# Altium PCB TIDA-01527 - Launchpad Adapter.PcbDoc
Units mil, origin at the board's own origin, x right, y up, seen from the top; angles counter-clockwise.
Board outline 2007.87 x 1181.1 mil, 2 copper layers (Top Layer, Bottom Layer), stack 62 mil thick; 19 components, 11 nets, 70 pads, 2 vias.
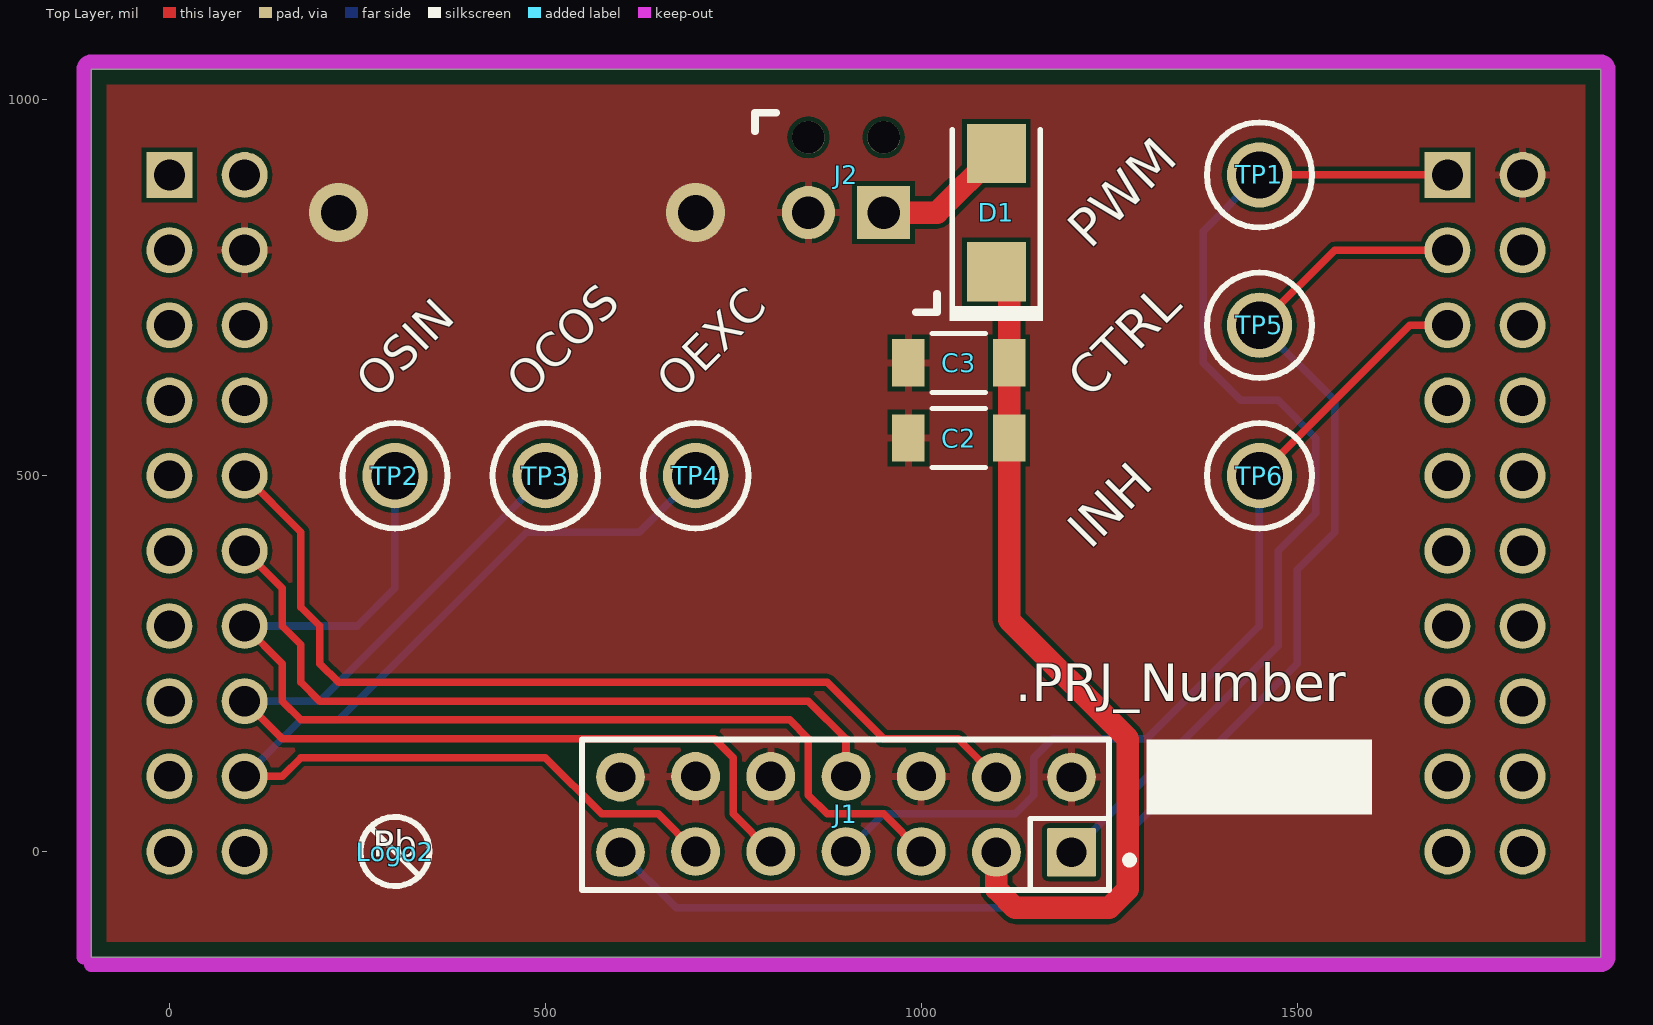
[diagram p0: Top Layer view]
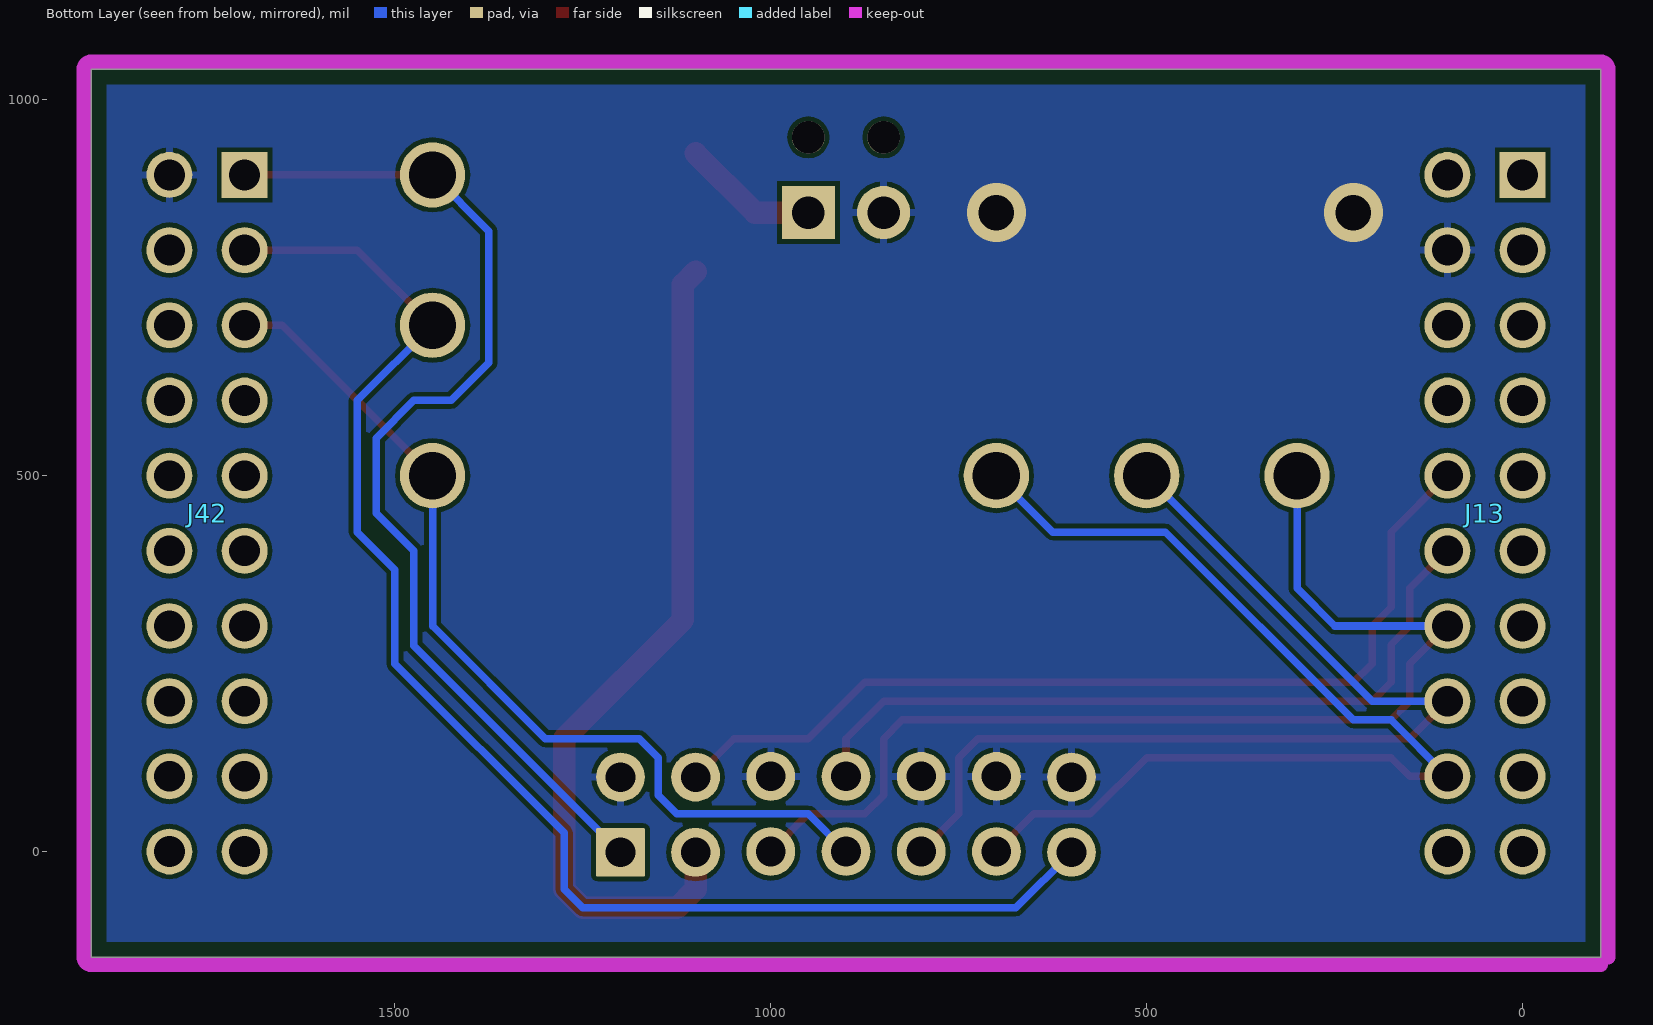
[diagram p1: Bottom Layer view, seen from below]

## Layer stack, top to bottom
Top Solder: solder mask 0.4, Solder Resist, Dk 3.5
Top Layer: signal copper 1.4
Dielectric1: core 59.2, FR-4, Dk 4.8
Bottom Layer: signal copper 1.4
Bottom Solder: solder mask 0.4, Solder Resist, Dk 3.5

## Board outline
-103.94,-140.55 1903.94,-140.55 1903.94,1040.55 -103.94,1040.55

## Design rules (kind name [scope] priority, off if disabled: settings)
Clearance Clearance_to_outline [All vs OnLayer('Keep-Out Layer')] p1: gap=20 ignorepadtopadclearanceinfootprint=FALSE except(0: Arc-Hole Track-Hole SMDPad-Hole THPad-Hole Via-Hole Fill-Hole Poly-Hole Region-Hole Text-Hole)
Clearance [All] p2: gap=6 ignorepadtopadclearanceinfootprint=FALSE except(0: Arc-Hole Track-Hole SMDPad-Hole THPad-Hole Via-Hole Fill-Hole Poly-Hole Region-Hole Text-Hole)
ComponentClearance ComponentClearance_J4&J5 [InComponent('J4') vs InComponent('J5')] p1: gap=0 collisioncheckmode=3 verticalgap=100000 showdistances=FALSE
ComponentClearance [All] p2: gap=10 collisioncheckmode=3 verticalgap=10 showdistances=FALSE
DiffPairsRouting [All] p1: maxlimit=393.7 minlimit=4.92 mostfreqgap=5.91 toplayer_minwidth=15 toplayer_maxwidth=15 toplayer_prefwidth=15 bottomlayer_minwidth=15 bottomlayer_maxwidth=15 bottomlayer_prefwidth=15 maxuncoupledlength=500
FabricationTestPointUsage FabricationTestPointUsage_1 [All] p1: valid=0 allowmultiple=FALSE
FabricationTestpoint FabricationTestpoint_1 [All] p1: side=3 testpointundercomponent=TRUE minsize=40 maxsize=100 preferedsize=60 minholesize=0 maxholesize=40 preferedholesize=32 testpointgrid=1 allowsidetop=TRUE allowsidebottom=TRUE usegrid=TRUE gridtolerance=0.01
HoleSize [All] p1: absolutevalues=TRUE maxlimit=236.22 minlimit=7.87 maxpercent=80.000 minpercent=20.000
HoleSize FabricationTestpoint [All] p2 off: absolutevalues=TRUE maxlimit=100 minlimit=1 maxpercent=80.000 minpercent=20.000
HoleSize FabricationTestPointUsage [All] p3 off: absolutevalues=TRUE maxlimit=100 minlimit=1 maxpercent=80.000 minpercent=20.000
PlaneClearance [All] p1: clearance=19.68
PlaneConnect [All] p1: planeconnectstyle=Relief reliefexpansion=15.75 reliefentries=4 reliefconductorwidth=5.91 reliefairgap=5.91
PolygonConnect PolygonConnect_via [IsVia] p1: connectstyle=Direct reliefconductorwidth=10 reliefentries=4 polygonreliefangle="90 Angle" airgapwidth=10
PolygonConnect [All] p2: connectstyle=Relief reliefconductorwidth=10 reliefentries=4 polygonreliefangle="90 Angle" airgapwidth=6
RoutingCorners [All] p1: cornerstyle=45-Degree minsetback=49.21 maxsetback=49.21
RoutingVias [All] p1: holewidth=12 width=28 viastyle="Through Hole" minholewidth=7.87 minwidth=17.72 maxholewidth=17.72 maxwidth=29.53
SilkToSilkClearance [All] p1: silktosilkclearance=0
SilkToSolderMaskClearance [IsPad] p1: minsilkscreentomaskgap=4 clearancetoexposedcopper=TRUE
SolderMaskExpansion SolderMaskExpansion_vias [IsVia] p1: expansion=-15
SolderMaskExpansion [All] p2: expansion=2.95
Width [All] p1: maxlimit=30 minlimit=8 preferedwidth=10
20 further rules are at their usual default settings.

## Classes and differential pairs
component class "TIDA-01527 - Launchpad Adapter_circuit": C2 C3 D1 J1 J2 J13 J42 TP1 TP2 TP3 TP4 TP5 TP6
component class "TIDA-01527 - Launchpad Adapter_Hardware": Logo2 Logo3 ZZ1 ZZ2 ZZ3 ZZ4
component class AssemblyNote: ZZ1 ZZ2 ZZ3 ZZ4

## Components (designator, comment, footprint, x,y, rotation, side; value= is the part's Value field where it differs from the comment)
C2 "GCM31CR72A105KA03" 1206_180 1050,550 r180 top value=1uF
C3 "GCM31CR72A105KA03" 1206_180 1050,650 r180 top value=1uF
D1 "SS16T3G" SMA 1100,850 r90 top value=60V
J1 "SSQ-107-03-G-D" SSQ-107-03-G-D 900,50 r0 top
J2 "1725656" CONN_1725656 900,850 r180 top
J13 "SSW-110-21-S-D" Samtec_SSW-110-x1-x-D 50,450 r270 bottom locked
J42 "SSW-110-21-S-D" Samtec_SSW-110-x1-x-D 1750,450 r270 bottom locked
Logo2 "Pb-Free Symbol" Pb-Free_Overlay_Small 300,0 r0 top
Logo3 "FCC disclaimer" FCC_disclaimer 1026.06,1229.45 r180 bottom
TP1 "5005" Keystone5005 1450,900 r0 top
TP2 "5005" Keystone5005 300,500 r0 top
TP3 "5005" Keystone5005 500,500 r0 top
TP4 "5005" Keystone5005 700,500 r0 top
TP5 "5005" Keystone5005 1450,700 r0 top
TP6 "5005" Keystone5005 1450,500 r0 top
ZZ1 "This Assembly Note is for PCB labels only" AssemblyNoteLabel 81.06,3797.45 r0 top
ZZ2 "These assemblies are ESD sensitive, ESD precautions shall be observed." AssemblyNote 81.06,3688.56 r0 top
ZZ3 "These assemblies must be clean and free from flux and all contaminants. Use of no clean flux is not acceptable." AssemblyNote 81.06,3600.01 r0 top
ZZ4 "These assemblies must comply with workmanship standards IPC-A-610 Class 2, unless otherwise specified." AssemblyNote 81.06,3511.45 r0 top

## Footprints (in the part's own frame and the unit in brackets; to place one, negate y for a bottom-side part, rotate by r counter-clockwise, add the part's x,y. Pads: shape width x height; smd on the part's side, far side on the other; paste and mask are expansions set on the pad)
1206_180 [mm] "1206_180"
  rect 1.1x1.6 smd: 1(-1.7,0) 2(1.7,0)
  silkscreen extent -0.9,-1 0.9,1, body extent -1.75,-0.95 1.75,0.95, height 1.8
AssemblyNote [mil] "Assembly Note"
AssemblyNoteLabel [mil] "Assembly Note for PCB Labels"
CONN_1725656 [mm] "Phoenix Contact"
  rect 1.8x1.8 hole 1.1: 1(-1.27,0)
  round 1.8 hole 1.1: 2(1.27,0)
  round 1.1 hole 1.1 unplated: MH1(-1.275,-2.54) MH2(1.27,-2.54)
  silkscreen extent -3.08,-3.37 3.08,3.37, body extent -2.77,-3.1 2.77,3.1, height 8.52
FCC_disclaimer [mil]
Keystone5005 [mil] "Keystone Compact loops"
  round 87 hole 63: 1(0,0)
  silkscreen extent -70,-70 70,70, body extent -63,-63 62,63, height 225
Pb-Free_Overlay_Small [mil]
  silkscreen extent -46,-46 46,46
Samtec_SSW-110-x1-x-D [mm] "Receptacle, 2.54mm, 10x2, TH"
  rect 1.55x1.55 hole 1.04: 1(-11.43,1.27)
  round 1.55 hole 1.04: 2(-11.43,-1.27) 3(-8.89,1.27) 4(-8.89,-1.27) 5(-6.35,1.27) 6(-6.35,-1.27) 7(-3.81,1.27) 8(-3.81,-1.27) 9(-1.27,1.27) 10(-1.27,-1.27) 11(1.27,1.27) 12(1.27,-1.27) 13(3.81,1.27) 14(3.81,-1.27) 15(6.35,1.27) 16(6.35,-1.27) 17(8.89,1.27) 18(8.89,-1.27) 19(11.43,1.27) 20(11.43,-1.27)
  body extent -12.95,-2.48 12.95,2.48, height 8.51
SMA [mm] "Molded Diode, 2-Leads, Body 4.3x2.6mm, IPC Medium Density, based on OnSemi component dimensions and land pattern"
  rect 2x2 smd: 1(-2,0) 2(2,0)
  silkscreen extent -3.66,-1.57 2.79,1.57, body extent -2.6,-1.3 2.6,1.3, height 2.42
SSQ-107-03-G-D [mm] "Samtec socket, 100 mil spacing, 2x7"
  rrect6% 1.65x1.65 hole 1: 1(7.62,-1.295)
  round 1.65 hole 1: 2(7.62,1.245) 3(5.08,-1.295) 4(5.08,1.245) 5(2.54,-1.27) 6(2.54,1.27) 7(0,-1.27) 8(0,1.27) 9(-2.54,-1.27) 10(-2.54,1.27) 11(-5.08,-1.27) 12(-5.08,1.27) 13(-7.62,-1.295) 14(-7.62,1.245)
  silkscreen extent -8.92,-2.57 9.71,2.52, body extent -9.14,-2.5 9.14,2.45, height 8.41

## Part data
C2 C3: "CAP, CERM, 1 µF, 100 V,+/- 10%, X7R, AEC-Q200 Grade 1, 1206", Cap_Case=1206, Manufacturer=MuRata, Supplier Part Number 1=GCM31CR72A105KA03L-ND, TempCo=X7R, Tolerance_%=10, Value2=100V, ValueDisplayed=1µF
D1: "Diode, Schottky, 60 V, 1 A, SMA", Manufacturer="ON Semiconductor", Supplier Part Number 1=SS16T3GOSCT-ND, Value1=1A, Value2=0.72V
J1: "Receptacle, 100mil, 7x2, Gold, TH", Manufacturer=Samtec, Supplier Part Number 1=SAM1196-07-ND
J2: "Terminal Block, 100mil, 2x1, 6A, 63V, TH", Manufacturer="Phoenix Contact", Supplier Part Number 1=651-1725656
J13 J42: "Receptacle, 2.54mm, 10x2, Gold, TH", Color=Black, Manufacturer=Samtec, Supplier Part Number 1=SAM1223-10-ND
Logo2: library part Pb-Free
Logo3: library part FCC_disclaimer, "FCC_disclaimer"
TP1 TP2 TP3 TP4 TP5 TP6: "Test Point, Compact, Red, TH", Color=Red, Manufacturer=Keystone, Supplier Part Number 1=36-5005-ND
ZZ1: library part AssemblyNoteLabel, Alternate Manufacturer=-
ZZ2 ZZ3 ZZ4: library part AssemblyNote, Alternate Manufacturer=-

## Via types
v1: diameter 78.74, hole 47.24, Top Layer to Bottom Layer, 2 vias

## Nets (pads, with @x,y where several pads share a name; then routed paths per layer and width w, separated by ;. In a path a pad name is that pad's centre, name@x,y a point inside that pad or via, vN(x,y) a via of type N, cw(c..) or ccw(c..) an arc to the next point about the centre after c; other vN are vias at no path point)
CTRL: J1.13 J42.3 TP5.1 | length 1912.8
  Top Layer w10: TP5.1 1550,800 J42.3
  Bottom Layer w10: J1.13 674,-75 1250,-75 1275,-50 1275,25 1500,250 1500,375 1550,425 1550,600 TP5.1
GND: C2.2 C3.2 J1.2 J1.6 J1.10 J1.12 J1.14 J2.2 J13.4 J42.2
  other v1: 225,850 700,850
INH: J1.7 J42.5 TP6.1 | length 1236.4
  Top Layer w10: TP6.1 1650,700 J42.5
  Bottom Layer w10: J1.7 950,50 1125,50 1150,75 1150,125 1175,150 1300,150 1450,300 TP6.1
NetD1_2: D1.2 J2.1 | length 182.6
  Top Layer w30: J2.1 1021.26,850 D1.2
OCOS: J1.9 J13.16 TP3.1 | length 1351
  Top Layer w10: J13.16 150,150 725,150 750,125 750,50 J1.9
  Bottom Layer w10: J13.16 200,200 TP3.1
OEXC: J1.11 J13.18 TP4.1 | length 1427.8
  Top Layer w10: J13.18 150,100 175,125 500,125 575,50 650,50 J1.11
  Bottom Layer w10: J13.18 175,175 225,175 475,425 625,425 TP4.1
OSIN: J1.5 J13.14 TP2.1 | length 1468.2
  Top Layer w10: J13.14 150,250 150,200 175,175 825,175 850,150 850,75 875,50 950,50 J1.5
  Bottom Layer w10: J13.14 250,300 300,350 TP2.1
PWM: J1.1 J42.1 TP1.1 | length 1408.1
  Top Layer w10: TP1.1 J42.1
  Bottom Layer w10: J1.1 1475,274 1475,400 1525,450 1525,550 1475,600 1425,600 1375,650 1375,825 TP1.1
VCC: C2.1 C3.1 D1.1 J1.3 | length 1138.5
  Top Layer w30: J1.3 1100,-50 1125,-75 1250,-75 1275,-50 1275,150 1116.93,308.07 C2.1 C3.1 1116.93,754.33 D1.1
VREF: J1.4 J13.10 | length 1254
  Top Layer w10: J13.10 175,425 175,325 200,300 200,250 225,225 875,225 950,150 1049,150 J1.4
VREF1/2: J1.8 J13.12 | length 1012.1
  Top Layer w10: J13.12 150,350 150,300 175,275 175,225 200,200 850,200 900,150 J1.8
pads on no net: J2.MH1 J2.MH2 J13.1 J13.2 J13.3 J13.5 J13.6 J13.7 J13.8 J13.9 J13.11 J13.13 J13.15 J13.17 J13.19 J13.20 J42.4 J42.6 J42.7 J42.8 J42.9 J42.10 J42.11 J42.12 J42.13 J42.14 J42.15 J42.16 J42.17 J42.18 J42.19 J42.20

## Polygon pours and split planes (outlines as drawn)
GND on Top Layer "Top Layer-No Net" (solid, pour order 0): -103.94,-140.55 1903.94,-140.55 1903.94,1040.55 -103.94,1040.55
GND on Bottom Layer "Bottom Layer-No Net" (solid, pour order 2): -103.94,-140.55 1903.94,-140.55 1903.94,1040.55 -103.94,1040.55

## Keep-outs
Keep-Out Layer:
  lines w19.68: -113.78,-140.55 -113.78,1040.55 ; -103.94,-150.39 1903.94,-150.39 ; -113.78,1040.55 cw(c-103.94,1040.55) -103.94,1050.39 ; -113.78,1040.55 cw(c-103.94,1040.55) -103.94,1050.39 ; -103.94,1050.39 1903.94,1050.39 ; 1903.94,-150.39 ccw(c1903.94,-140.55) 1913.78,-140.55 ; 1903.94,-150.39 ccw(c1903.94,-140.55) 1913.78,-140.55 ; 1903.94,1050.39 cw(c1903.94,1040.55) 1913.78,1040.55 ; 1903.94,1050.39 cw(c1903.94,1040.55) 1913.78,1040.55 ; 1913.78,-140.55 1913.78,1040.55
  text ".Layer_Name" at 473.06,-999.04 h60

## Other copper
Top Layer:
  text ".Layer_Name" at 473.06,-999.04 h60
Bottom Layer:
  text ".Layer_Name" at 473.06,-999.04 h60

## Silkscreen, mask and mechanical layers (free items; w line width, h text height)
Top Overlay:
  region: 1600,149.21 1300,149.21 1300,49.21 1600,49.21
  text "PWM" at 1225,800 h50 r45
  text "OSIN" at 275,600 h45 r45
  text "OCOS" at 475,600 h45 r45
  text "OEXC" at 675,600 h45 r45
  text "CTRL" at 1225,600 h50 r45
  text "INH" at 1225,400 h50 r45
  text ".PRJ_Number" at 1125,200 h50
  text ".Layer_Name" at 473.06,-999.04 h60
Bottom Overlay:
  text ".Layer_Name" at 473.06,-999.04 h60
Top Paste:
  text ".Layer_Name" at 473.06,-999.04 h60
Bottom Paste:
  text ".Layer_Name" at 473.06,-999.04 h60
Top Solder:
  rectangle: 175,750 750,950
  text ".Layer_Name" at 473.06,-999.04 h60
  text ".Layer_Name" at 473.06,-999.04 h60
Bottom Solder:
  text ".Layer_Name" at 473.06,-999.04 h60
Drill Guide:
  text ".Layer_Name" at 473.06,-999.04 h60
M1 Board Outline:
  the board outline again, w8
  text ".Layer_Name" at 473.06,-999.04 h60
M2 Board Dimensions:
  rectangle: -103.94,-415.55 21.06,-290.55
  rectangle: 21.06,-540.55 396.06,-415.55
  lines w7: -103.94,-415.55 896.06,-415.55 ; 21.06,-540.55 21.06,-290.55 ; 146.06,-540.55 146.06,-290.55 ; 396.06,-540.55 396.06,-290.55 ; 646.06,-540.55 646.06,-290.55 ; -103.94,-540.55 896.06,-540.55 896.06,-290.55 -103.94,-290.55 -103.94,-540.55
  text ".Layer_Name" at 473.06,-999.04 h60
M3 3D STEP Top:
  text ".Layer_Name" at 473.06,-999.04 h60
M4 3D STEP Bottom:
  text ".Layer_Name" at 473.06,-999.04 h60
M5 Assembly Top:
  lines w10: -395.94,-1070.72 6204.06,-1070.72 ; -395.94,-867.38 6206.06,-867.38 ; -395.94,-664.05 -395.94,-1274.05 3609.06,-1274.05 6206.06,-1274.05 6206.06,-664.05 -395.44,-664.05 -395.44,-1274.05 1180.06,-1274.05 ; 2069.06,-1274.05 2069.06,-664.05 ; 3336.06,-867.38 3336.06,-664.05 ; 4176.06,-867.38 4176.06,-664.05 ; 4798.06,-1280.55 4798.06,-1077.72
  text "COMPONENTS MARKED 'DNP' SHOULD NOT BE POPULATED." at 1049.56,-459.05 h60
  text "ASSEMBLY VARIANT:" at 1049.06,-574.55 h60
  text ".VariantName" at 2085.06,-574.55 h60
  text "PCB VIEWED FROM TOP SIDE" at -332.44,-796.22 h60
  text "BOARD #:" at 2144.06,-796.22 h60
  text ".PRJ_Number" at 2689.56,-796.22 h60
  text "REV:" at 3534.06,-796.22 h60
  text ".PCB_Rev" at 3825.56,-796.22 h60
  text "SVN REV:" at 4372.06,-796.22 h60
  text ".VersionControl_RevNumber" at 4878.06,-796.22 h60
  text "TID #:" at 2144.06,-999.55 h60
  text ".TID" at 2689.56,-999.55 h60
  text "PLOT NAME =" at -332.44,-1204.89 h60
  text ".plot_File_Name" at 473.06,-1204.89 h60
  text "GENERATED    :" at 2146.06,-1204.89 h60
  text ".Print_Date" at 3015.56,-1204.89 h60
  text ".Print_Time" at 3744.56,-1204.89 h60
  text "TEXAS INSTRUMENTS" at 5009.06,-1204.89 h60
M6 Assembly Bottom:
  lines w10: -396.44,-867.88 6205.56,-867.88 ; -394.44,-1071.22 6205.56,-1071.22 ; 1011.56,-1281.05 1011.56,-1078.22 ; 1633.56,-867.88 1633.56,-664.55 ; 2473.56,-867.88 2473.56,-664.55 ; 3740.56,-1274.55 3740.56,-664.55 ; 4629.56,-1274.55 6205.06,-1274.55 6205.06,-664.55 -396.44,-664.55 -396.44,-1274.55 2200.56,-1274.55 6205.56,-1274.55 6205.56,-664.55
  text "COMPONENTS MARKED 'DNP' SHOULD NOT BE POPULATED." at 5998.06,-458.55 h60
  text ".VariantName" at 4954.06,-574.55 h60
  text "ASSEMBLY VARIANT:" at 5993.06,-574.55 h60
  text ".VersionControl_RevNumber" at 931.56,-796.72 h60
  text "SVN REV:" at 1437.56,-796.72 h60
  text ".PCB_Rev" at 1984.06,-796.72 h60
  text "REV:" at 2275.56,-796.72 h60
  text ".PRJ_Number" at 3120.06,-796.72 h60
  text "BOARD #:" at 3665.56,-796.72 h60
  text "PCB VIEWED FROM BOTTOM SIDE" at 6142.06,-796.72 h60
  text ".TID" at 3120.06,-1000.05 h60
  text "TID #:" at 3665.56,-1000.05 h60
  text "TEXAS INSTRUMENTS" at 800.56,-1205.39 h60
  text ".Print_Time" at 2065.06,-1205.39 h60
  text ".Print_Date" at 2794.06,-1205.39 h60
  text "GENERATED    :" at 3663.56,-1205.39 h60
  text ".plot_File_Name" at 5336.56,-1205.39 h60
  text "PLOT NAME =" at 6142.06,-1205.39 h60
M9 Title Sheet:
  drawing of 57 lines, arcs and shapes, not listed
  text "1" at 635.9,7895.95 h70
  text "2" at 3131.56,7895.95 h70
  text "3" at 5620.91,7895.95 h70
  text "4" at 8127.57,7895.95 h70
  text "5" at 10626.56,7895.95 h70
  text "6" at 13131.56,7895.95 h70
  text "A" at -520.44,6752.95 h70
  text "A" at 14279.56,6752.95 h70
  text "B" at -520.44,4372.95 h70
  text "B" at 14279.56,4372.95 h70
  text "C" at -520.44,1997.95 h70
  text "C" at 14279.56,1997.95 h70
  text "PROJECT TITLE:" at 11239.56,136.95 h45
  text ".PRJ_Title" at 11289.56,3.62 h70
  text "DESIGNED FOR:" at 11239.56,-164.05 h45
  text ".PRJ_Customer" at 11289.56,-304.05 h70
  text "D" at -520.44,-372.05 h70
  text "D" at 14279.56,-372.05 h70
  text "FILE NAME:" at 11239.56,-464.05 h45
  text ".PCB_File_Name_No_Path" at 11289.56,-584.05 h70
  text "Texas Instruments (TI) and/or its licensors do not warrant the accuracy or completeness of this specification" at 6270.06,-745.89 h45
  text "ENGINEER:" at 11239.56,-754.05 h45
  text "LAYOUT BY:" at 12744.56,-754.05 h45
  text "or any information contained therein. TI and/or its licensors do not warrant that this design will meet" at 6225.08,-858.56 h45
  text ".PRJ_Engineer" at 11289.56,-909.04 h70
  text ".PCB_Layout" at 12795.06,-909.04 h70
  text "the specifications, will be suitable for your application or fit for any particular purpose, or will operate in" at 6225.08,-971.22 h45
  text ".Layer_Name" at 473.06,-999.04 h60
  text "ALTIUM DESIGNER VERSION:" at 12744.56,-1064.05 h45
  text "an implementation. TI and/or its licensors do not warrant that the design is production worthy. You should" at 6225.08,-1083.89 h45
  text "completely validate and test your design implementation to confirm the system functionality for your application." at 6270.06,-1196.55 h45
  text ".print_Scale" at 11289.56,-1197.38 h70
  text ".Application_BuildNumber" at 12795.06,-1197.38 h70
  text "1" at 635.9,-1404.05 h70
  text "2" at 3131.56,-1404.05 h70
  text "3" at 5620.91,-1404.05 h70
  text "4" at 8127.57,-1404.05 h70
  text "5" at 10626.56,-1404.05 h70
  text "6" at 13131.56,-1404.05 h70
M10 Fab Notes:
  drawing of 173 lines, arcs and shapes, not listed
  text "DESIGN INFORMATION" at 12273.08,6060.45 h60
  text "MIN. TRACK WIDTH:" at 11628.52,5880.45 h60
  text "8" at 12724.76,5880.45 h60
  text "MIL" at 12879.52,5880.45 h60
  text "MIN. CLEARANCE:" at 11628.52,5748.45 h60
  text "0.2" at 12664.76,5748.45 h60
  text "mm" at 12879.52,5748.45 h60
  text "MIN. VIA PAD SIZE:" at 11628.52,5616.45 h60
  text "24" at 12694.77,5616.45 h60
  text "MIL" at 12879.52,5616.45 h60
  text "0.05mm (2MIL)" at 12323.52,5474.74 h60
  text "MINIMUM ANNULAR RING" at 11299.29,5470.45 h60
  text "EXTERNAL" at 13031.52,5470.45 h60
  text "PER" at 11499.29,5352.45 h60
  text "IPC-D-275 CLASS 2 LEVEL C" at 11719.29,5352.45 h60
  text "MIL, HOLES" at 13207.52,5240.16 h60
  text "+/-" at 12815.06,5239.45 h60
  text "+/-" at 13669.06,5239.45 h60
  text "REGISTRATION TOLERANCES:" at 11299.29,5234.45 h60
  text "METAL" at 12499.06,5234.45 h60
  text "5" at 13075.26,5234.45 h60
  text "3" at 13908.26,5234.45 h60
  text "MIL" at 14024.52,5234.45 h60
  text "+/-" at 13669.06,5121.45 h60
  text "HOLE SIZE TOLERANCE (UNLESS OTHERWISE SPECIFIED):" at 11299.29,5116.45 h60
  text "3" at 13908.26,5116.45 h60
  text "MIL" at 14024.52,5116.45 h60
  text "MATERIAL:" at 11224.52,4906.99 h60
  text "FR-4 High Tg" at 12210.97,4766.66 h60
  text "FR-408" at 11645.52,4758.09 h60
  text "OTHER" at 13133.52,4758.09 h60
  text "X" at 12056.06,4754.45 h60
  text "62 MIL (1.6mm) +/-10%" at 11965.62,4595.37 h60
  text "THICKNESS:" at 11299.29,4591.09 h60
  text "X" at 11837.46,4591.09 h60
  text "OTHER" at 13250.52,4591.09 h60
  text "TOLERANCE:" at 11299.29,4433.09 h60
  text "X" at 12138.6,4433.09 h60
  text "ANSI IPC-6012 TYPE 3 CLASS 2" at 12325.54,4433.09 h60
  text "OTHER +/-" at 12325.52,4277.09 h60
  text "BOW & TWIST:" at 11299.29,4120.09 h60
  text "X" at 12138.6,4120.09 h60
  text "ANSI IPC-6012 TYPE 3 CLASS 2" at 12325.54,4120.09 h60
  text "OTHER +/-" at 12325.52,3961.58 h60
  text "DRILLING:" at 11224.52,3823.09 h60
  text "REFERENCE:" at 11299.29,3706.09 h60
  text "X" at 11947.52,3706.09 h60
  text "AS SHOWN" at 12134.52,3706.09 h60
  text "X" at 12848.52,3706.09 h60
  text "NC_DRILL FILES" at 12985.52,3706.09 h60
  text "PTH MIN COPPER THICKNESS:" at 11299.29,3548.09 h60
  text "X" at 12649.52,3548.09 h60
  text "1MIL" at 12786.52,3548.09 h60
  text "OTHER" at 13283.52,3548.09 h60
  text "BOARD FINISH:" at 11224.52,3389.09 h60
  text "SILKSCREEN:" at 11379.74,3271.09 h60
  text "X" at 12328.52,3271.09 h60
  text "TOP" at 12454.52,3271.09 h60
  text "X" at 12838.52,3271.09 h60
  text "BOTTOM" at 12965.52,3271.09 h60
  text "SILKSCREEN COLOR:" at 11379.74,3104.09 h60
  text "X" at 12327.48,3104.09 h60
  text "WHITE" at 12454.52,3104.09 h60
  text "OTHER" at 12965.52,3104.09 h60
  text "X" at 12458.49,2944.89 h60
  text "GREEN" at 12585.52,2944.89 h60
  text "OTHER" at 13203.52,2944.89 h60
  text "SOLDER RESIST COLOR:" at 11379.74,2934.09 h60
  text "X" at 12458.49,2774.89 h60
  text "MATTE" at 12585.52,2774.89 h60
  text "SEMI-GLOSS" at 13203.06,2774.25 h60
  text "IMMERSION GOLD (ENIG)" at 12285.52,2586.37 h60
  text "ENEPIG" at 13623.06,2583.09 h60
  text "SURFACE FINISH:" at 11224.52,2582.09 h60
  text "X" at 12098.58,2582.09 h60
  text "IMM. TIN/SILVER OR EQUIV" at 11554.06,2425.09 h60
  text "OTHER" at 12985.52,2425.09 h60
  text "ARRAY/PANEL:" at 11224.52,2246.09 h60
  text "CUT AND TRIM PER M1 BOARD OUTLINE" at 12285.52,2241.8 h60
  text "N.C. ROUTE" at 12285.52,2090.09 h60
  text "X" at 12964.52,2090.09 h60
  text "V. SCORE" at 13151.52,2090.09 h60
  text "CERTIFICATION:" at 11224.52,1953.09 h60
  text "MATERIALS AND WORKMANSHIP FOR ALL PCBS" at 11949.52,1953.09 h60
  text "TO MEET OR EXCEED THE REQUIREMENTS OF:" at 11949.52,1855.09 h60
  text "X" at 11576.03,1718.58 h60
  text "ANSI IPC-A-600F CLASS ->" at 11715.03,1718.58 h60
  text "X" at 13354.08,1718.58 h60
  text "2" at 13473.03,1718.58 h60
  text "1" at 13158.03,1717.09 h60
  text "3" at 13827.03,1717.09 h60
  text "X" at 12390.08,1559.09 h60
  text "RoHS" at 12527.03,1559.09 h60
  text "OTHER" at 13171.43,1559.09 h60
  text "PER ORDER" at 13568.49,1559.09 h60
  text "ALL BOARDS MUST MEET OR EXCEED UL94-V0 REQUIREMENTS." at 11252.06,1393.45 h60
  text "PCB MUST BEAR THE UL94V-0 UL REGISTERED MATERIAL ID NUMBER" at 11252.06,1273.45 h60
  text "ADDITIONAL REQUIREMENTS:" at 11224.52,1100.09 h60
  text "MICROSECTION:" at 11299.29,985.09 h60
  text "YES" at 12205.03,985.09 h60
  text "REQUIRED" at 13066.52,828.94 h60
  text "BARE BOARD ELEC. TEST:" at 11299.29,826.09 h60
  text "NONE" at 12605.03,826.09 h60
  text "X" at 12939.52,826.09 h60
  text "PER ORDER" at 13658.52,826.09 h60
  text ".Layer_Name" at 473.06,-999.04 h60
M11 Gerber Information:
  lines w10: -395.94,-1070.72 6204.06,-1070.72 ; -395.94,-867.38 6206.06,-867.38 ; -395.94,-664.05 -395.94,-1274.05 3609.06,-1274.05 6206.06,-1274.05 6206.06,-664.05 -395.44,-664.05 -395.44,-1274.05 1180.06,-1274.05 ; 2069.06,-1274.05 2069.06,-664.05 ; 3336.06,-867.38 3336.06,-664.05 ; 4176.06,-867.38 4176.06,-664.05 ; 4798.06,-1280.55 4798.06,-1077.72
  text "ALL ARTWORK VIEWED FROM TOP SIDE" at -332.44,-796.22 h60
  text "BOARD #:" at 2144.06,-796.22 h60
  text ".PRJ_Number" at 2689.56,-796.22 h60
  text "REV:" at 3534.06,-796.22 h60
  text ".PCB_Rev" at 3825.56,-796.22 h60
  text "SVN REV:" at 4372.06,-796.22 h60
  text ".VersionControl_RevNumber" at 4878.06,-796.22 h60
  text "LAYER NAME =" at -332.44,-999.04 h60
  text "TID #:" at 2144.06,-999.55 h60
  text ".TID" at 2689.56,-999.55 h60
  text "PLOT NAME =" at -332.44,-1204.89 h60
  text ".plot_File_Name" at 473.06,-1204.89 h60
  text "GENERATED    :" at 2146.06,-1204.89 h60
  text ".Print_Date" at 3015.56,-1204.89 h60
  text ".Print_Time" at 3744.56,-1204.89 h60
  text "TEXAS INSTRUMENTS" at 5009.06,-1204.89 h60
M12 Stackup:
  drawing of 191 lines, arcs and shapes, not listed
  text "Layer" at 9686.41,7689.45 h60
  text "Name" at 10096.32,7689.45 h60
  text "Material" at 11026.06,7689.45 h60
  text "Thickness" at 11885.83,7689.45 h60
  text "Constant" at 12535.67,7689.45 h60
  text "Board Layer Stack" at 13105.53,7689.45 h60
  text "1" at 9686.41,7569.45 h60
  text "Top Overlay" at 10096.32,7569.45 h60
  text "2" at 9686.41,7449.45 h60
  text "Top Solder" at 10096.32,7449.45 h60
  text "Solder Resist" at 11026.06,7449.45 h60
  text "0.40mil" at 11885.83,7449.45 h60
  text "3.5" at 12535.67,7449.45 h60
  text "3" at 9686.41,7329.45 h60
  text "Top Layer" at 10096.32,7329.45 h60
  text "Copper" at 11026.06,7329.45 h60
  text "1.40mil" at 11885.83,7329.45 h60
  text "4" at 9686.41,7209.45 h60
  text "Dielectric1" at 10096.32,7209.45 h60
  text "FR-4" at 11026.06,7209.45 h60
  text "59.20mil" at 11885.83,7209.45 h60
  text "4.8" at 12535.67,7209.45 h60
  text "5" at 9686.41,7089.45 h60
  text "Bottom Layer" at 10096.32,7089.45 h60
  text "Copper" at 11026.06,7089.45 h60
  text "1.40mil" at 11885.83,7089.45 h60
  text "6" at 9686.41,6969.45 h60
  text "Bottom Solder" at 10096.32,6969.45 h60
  text "Solder Resist" at 11026.06,6969.45 h60
  text "0.40mil" at 11885.83,6969.45 h60
  text "3.5" at 12535.67,6969.45 h60
  text "7" at 9686.41,6849.45 h60
  text "Bottom Overlay" at 10096.32,6849.45 h60
  text ".Layer_Name" at 473.06,-999.04 h60
M13 Component Bodies Top:
  text ".Layer_Name" at 473.06,-999.04 h60
M14 Component Bodies Bottom:
  text ".Layer_Name" at 473.06,-999.04 h60
M15 Courtyards Top:
  text ".Layer_Name" at 473.06,-999.04 h60
M16 Courtyards Bottom:
  text ".Layer_Name" at 473.06,-999.04 h60
Drill Drawing:
  circle w10: c2341.98,-74.12 r27.63
  lines w10: 2314.36,-336.57 2328.17,-336.57 2341.98,-350.38 2355.8,-336.57 2369.61,-336.57 2355.8,-322.76 2369.61,-308.94 2355.8,-308.94 2341.98,-295.13 2328.17,-308.94 2314.36,-308.94 2328.17,-322.76 2314.36,-336.57 ; 2314.36,-212.25 2328.17,-212.25 2328.17,-226.06 2355.8,-226.06 2355.8,-212.25 2369.61,-212.25 2369.61,-184.62 2355.8,-184.62 2355.8,-170.81 2328.17,-170.81 2328.17,-184.62 2314.36,-184.62 2314.36,-212.25 ; 2314.36,22.58 2341.98,36.39 2369.61,22.58 2355.8,50.2 2369.61,77.83 2341.98,64.02 2314.36,77.83 2328.17,50.2 2314.36,22.58 ; 2314.36,146.9 2369.61,146.9 2369.61,202.15 2314.36,202.15 2314.36,146.9 ; 2314.36,326.47 2369.61,326.47 2341.98,271.22 2314.36,326.47
  lines w12: 2264.27,-387.68 4242.29,-387.68 ; 2264.27,358.24 4242.29,358.24 ; 2602.13,-512 2602.13,482.56 ; 2934.13,-512 2934.13,482.56 ; 3570.69,-512 3570.69,482.56 ; 3829.83,-512 3829.83,482.56 ; 2264.27,-512 4242.29,-512 4242.29,482.56 2264.27,482.56 2264.27,-512
  text "Symbol" at 2338.86,395.54 h72
  text "Quantity" at 2639.43,395.54 h72
  text "Finished Hole Size" at 2971.43,395.54 h72
  text "Plated" at 3607.99,395.54 h72
  text "Hole Type" at 3867.13,395.54 h72
  text "2" at 2639.43,271.22 h60
  text "43.31mil (1.100mm)" at 2971.43,271.22 h60
  text "NPTH" at 3607.99,271.22 h60
  text "Round" at 3867.13,271.22 h60
  text "14" at 2639.43,146.9 h60
  text "39.37mil (1.000mm)" at 2971.43,146.9 h60
  text "PTH" at 3607.99,146.9 h60
  text "Round" at 3867.13,146.9 h60
  text "40" at 2639.43,22.58 h60
  text "40.95mil (1.040mm)" at 2971.43,22.58 h60
  text "PTH" at 3607.99,22.58 h60
  text "Round" at 3867.13,22.58 h60
  text "2" at 2639.43,-101.74 h60
  text "43.31mil (1.100mm)" at 2971.43,-101.74 h60
  text "PTH" at 3607.99,-101.74 h60
  text "Round" at 3867.13,-101.74 h60
  text "2" at 2639.43,-226.06 h60
  text "47.24mil (1.200mm)" at 2971.43,-226.06 h60
  text "PTH" at 3607.99,-226.06 h60
  text "Round" at 3867.13,-226.06 h60
  text "6" at 2639.43,-350.38 h60
  text "63.00mil (1.600mm)" at 2971.43,-350.38 h60
  text "PTH" at 3607.99,-350.38 h60
  text "Round" at 3867.13,-350.38 h60
  text "66 Total" at 2639.43,-474.7 h60
  text ".Layer_Name" at 473.06,-999.04 h60

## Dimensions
-103.94,-540.55 to 896.06,-540.55 on M2 Board Dimensions
-103.94,-140.55 to -103.94,1040.55 on M2 Board Dimensions
-103.94,-140.55 to 1903.94,-140.55 on M2 Board Dimensions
